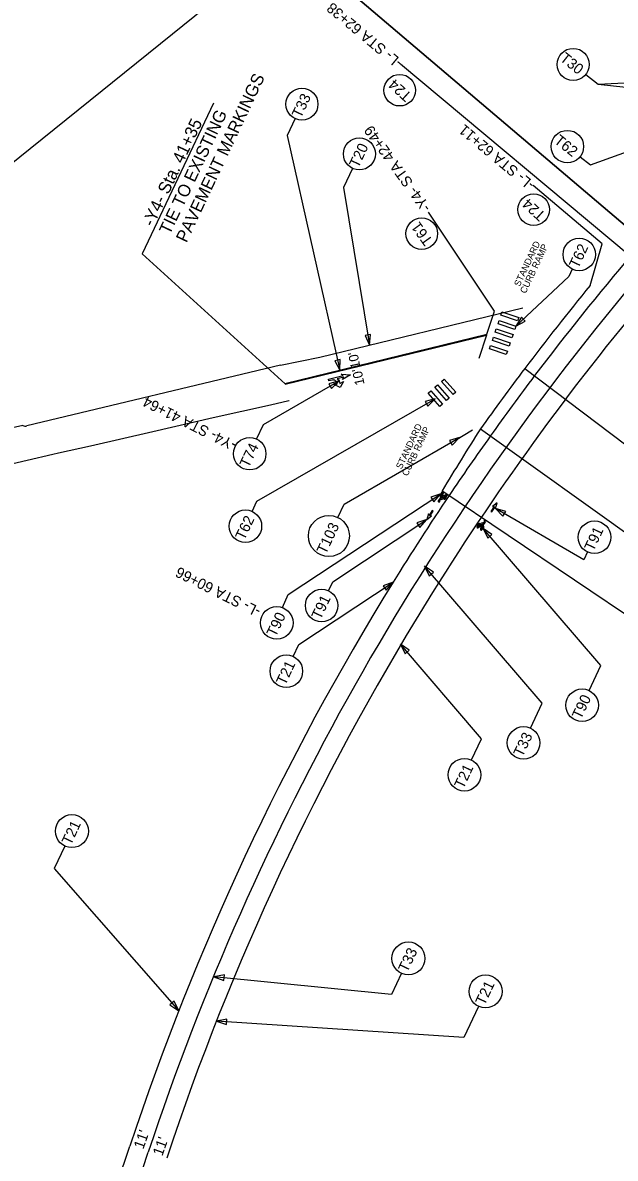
# Model space of a CAD drawing. Extents: x 553958 to 562499, y 493978 to 516388.
# Drawn here: x 557275 to 557610, y 506244 to 506887 of the extents above; entities that cross this region are included whole.
import ezdxf

# ---------------------------------------------------------------- set-up
doc = ezdxf.new("R2010")
doc.units = 0
for name, color, linetype in [('Prop Approach Slab', 7, 'Continuous'), ('Prop Conc 4in Sidewalk', 7, 'Continuous'), ('Prop Drainage Structure Gutter Shoulder Berm Label', 7, 'Continuous'), ('Prop EOT', 7, 'Continuous'), ('Prop Erosion Rip Rap Class II Label', 7, 'Continuous'), ('Prop Horizontal Alignment Tick Small', 7, 'Continuous'), ('Prop SS Fill Line', 7, 'Continuous'), ('Raster_Level_0', 7, 'Continuous'), ('Scratch_Level_0', 7, 'Continuous'), ('Scratch_Level_4', 7, 'Continuous'), ('Sheet North Arrow CELL', 7, 'Continuous'), ('Sheet Plan CELL', 7, 'Continuous'), ('Sheet Plot Border Inside CELL', 7, 'Continuous'), ('Sheet Plot Border Outside CELL', 7, 'Continuous')]:
    doc.layers.add(name, color=color, linetype=linetype)

msp = doc.modelspace()

# ---------------------------------------------------------------- linework, layer by layer
at = {"layer": 'Prop Approach Slab'}
for p, q in [((557618.37, 506754.68), (557488.54, 506863.27)), ((557602.58, 506761.69), (557563.47, 506794.66)), ((557541.75, 506723.58), (557504.29, 506779.54)), ((557595.82, 506738.04), (557602.58, 506761.69)), ((557537.19, 506709.89), (557541.75, 506723.58)), ((557558.78, 506691.06), (557680.67, 506599.06)), ((557533.69, 506656.92), (557657.57, 506568.52)), ((557511.85, 506622.13), (557636.11, 506538.44))]:
    msp.add_line(p, q, dxfattribs=at)
msp.add_lwpolyline([(557382.6, 506841.24), (557342.32, 506756.01), (557423.09, 506682.42)], dxfattribs=at)
at = {"layer": 'Prop Drainage Structure Gutter Shoulder Berm Label'}
msp.add_lwpolyline([(557447.66, 506685.08), (557456.08, 506687.13), (557454.86, 506687.94), (557460.17, 506687.61), (557455.6, 506684.87), (557456.32, 506686.16), (557452.65, 506685.27), (557453.12, 506684.91), (557453.4, 506684.61), (557453.66, 506684.22), (557453.83, 506683.88), (557454, 506683.44), (557454.17, 506682.63), (557456.2, 506683.81), (557454.36, 506680.45), (557450.33, 506682.21), (557452.64, 506682.26), (557452.47, 506682.89), (557452.36, 506683.26), (557452.18, 506683.61), (557451.93, 506683.89), (557451.66, 506684.18), (557451.24, 506684.42), (557450.76, 506684.57), (557450.27, 506684.61), (557449.74, 506684.57), (557447.9, 506684.11)], close=True, dxfattribs=at)
msp.add_lwpolyline([(557447.66, 506685.08), (557456.08, 506687.13), (557454.86, 506687.94), (557460.17, 506687.61), (557455.6, 506684.87), (557456.32, 506686.16), (557452.65, 506685.27), (557453.12, 506684.91), (557453.4, 506684.61), (557453.66, 506684.22), (557453.83, 506683.88), (557454, 506683.44), (557454.17, 506682.63), (557456.2, 506683.81), (557454.36, 506680.45), (557450.33, 506682.21), (557452.64, 506682.26), (557452.47, 506682.89), (557452.36, 506683.26), (557452.18, 506683.61), (557451.93, 506683.89), (557451.66, 506684.18), (557451.24, 506684.42), (557450.76, 506684.57), (557450.27, 506684.61), (557449.74, 506684.57), (557447.9, 506684.11)], close=True, dxfattribs=at)
at = {"layer": 'Prop EOT'}
for centre, start, end in [((558769.28, 505775.3), 139.54257, 142.88486), ((558763.69, 505779.29), 140.61603, 142.88486), ((558807.61, 505844.36), 147.46868, 149.02608), ((558769.28, 505775.3), 144.49155, 146.0414)]:
    msp.add_arc(centre, 1511, start, end, dxfattribs=at)
at = {"layer": 'Prop Erosion Rip Rap Class II Label'}
for points in [[(557425.46, 506933.59), (557889.73, 506539.36), (558124.72, 506519.69), (558557.87, 506177.2), (558959.56, 506684.21), (558454.57, 507154), (558185.43, 507366.81), (557535.46, 507286.55), (557335.3, 506986.11)], [(557510.24, 505740.54), (557854.59, 506431.05), (557889.73, 506539.36), (557425.46, 506933.59), (557046.6, 506628.46), (556899.98, 506318.25), (557006.57, 505850.3)]]:
    msp.add_lwpolyline(points, close=True, dxfattribs=at)
at = {"layer": 'Prop Horizontal Alignment Tick Small'}
for p, q in [((557510, 506616.36), (557509.87, 506616.44)), ((557510, 506616.36), (557509.87, 506616.44)), ((557510.4, 506616.73), (557511.23, 506618.18)), ((557510.72, 506616.63), (557510.4, 506616.73)), ((557512.01, 506616.99), (557510.72, 506616.63)), ((557511.39, 506617.84), (557510.85, 506616.89)), ((557510.85, 506616.89), (557512.18, 506617.24)), ((557511.23, 506618.18), (557512.91, 506619.46)), ((557511.26, 506620.24), (557511.47, 506620.11)), ((557511.26, 506620.24), (557511.47, 506620.11)), ((557512.39, 506617.65), (557511.39, 506617.84)), ((557513.06, 506619.27), (557511.47, 506618.06)), ((557511.47, 506618.06), (557512.24, 506617.92)), ((557512.18, 506617.24), (557512.01, 506616.99)), ((557512.15, 506619.66), (557512.35, 506619.53)), ((557512.15, 506619.66), (557512.35, 506619.53)), ((557512.24, 506617.92), (557512.47, 506618.53)), ((557512.7, 506618.44), (557512.39, 506617.65)), ((557512.47, 506618.53), (557512.7, 506618.44)), ((557512.91, 506619.46), (557513.08, 506619.29)), ((557513.31, 506618.9), (557513.51, 506618.77)), ((557513.31, 506618.9), (557513.51, 506618.77)), ((557514.2, 506618.32), (557514.4, 506618.19)), ((557514.2, 506618.32), (557514.4, 506618.19)), ((557510.81, 506615.82), (557510.69, 506615.91)), ((557510.81, 506615.82), (557510.69, 506615.91)), ((557535.67, 506603.92), (557534.34, 506603.57)), ((557534.34, 506603.57), (557534.51, 506603.83)), ((557534.51, 506603.83), (557535.81, 506604.18)), ((557535.13, 506602.98), (557535.67, 506603.92)), ((557536.12, 506604.09), (557535.29, 506602.64)), ((557535.71, 506604.99), (557535.84, 506604.91)), ((557535.71, 506604.99), (557535.84, 506604.91)), ((557535.81, 506604.18), (557536.12, 506604.09)), ((557536.52, 506604.46), (557536.65, 506604.37)), ((557536.52, 506604.46), (557536.65, 506604.37)), ((557532.33, 506602.49), (557532.12, 506602.63)), ((557532.33, 506602.49), (557532.12, 506602.63)), ((557533.21, 506601.91), (557533.01, 506602.05)), ((557533.21, 506601.91), (557533.01, 506602.05)), ((557533.61, 506601.35), (557533.44, 506601.53)), ((557533.46, 506601.54), (557535.05, 506602.75)), ((557535.29, 506602.64), (557533.61, 506601.35)), ((557533.83, 506602.37), (557534.13, 506603.16)), ((557534.05, 506602.29), (557533.83, 506602.37)), ((557534.28, 506602.89), (557534.05, 506602.29)), ((557534.13, 506603.16), (557535.13, 506602.98)), ((557534.37, 506601.15), (557534.17, 506601.29)), ((557534.37, 506601.15), (557534.17, 506601.29)), ((557535.05, 506602.75), (557534.28, 506602.89)), ((557535.26, 506600.57), (557535.05, 506600.71)), ((557535.26, 506600.57), (557535.05, 506600.71))]:
    msp.add_line(p, q, dxfattribs=at)
for points in [[(557506.06, 506607.79), (557505.14, 506607.63), (557507, 506610.47), (557506.47, 506610.82), (557504.61, 506607.98), (557504.38, 506608.89), (557503.44, 506605.63)], [(557506.06, 506607.79), (557505.14, 506607.63), (557507, 506610.47), (557506.47, 506610.82), (557504.61, 506607.98), (557504.38, 506608.89), (557503.44, 506605.63)], [(557540.54, 506612.98), (557541.46, 506613.13), (557539.58, 506610.3), (557540.11, 506609.95), (557541.99, 506612.78), (557542.22, 506611.86), (557543.17, 506615.12)], [(557540.54, 506612.98), (557541.46, 506613.13), (557539.58, 506610.3), (557540.11, 506609.95), (557541.99, 506612.78), (557542.22, 506611.86), (557543.17, 506615.12)]]:
    msp.add_lwpolyline(points, close=True, dxfattribs=at)
for centre, radius, start, end in [((557510.34, 506616.13), 0.563, 146.77541, 326.77541), ((557510.34, 506616.13), 0.563, 146.77541, 326.77541), ((557510.34, 506616.13), 0.41, 326.77541, 146.77541), ((557536.18, 506604.68), 0.563, 326.77541, 146.77541), ((557536.18, 506604.68), 0.563, 326.77541, 146.77541), ((557536.18, 506604.68), 0.41, 146.77541, 326.77541)]:
    msp.add_arc(centre, radius, start, end, dxfattribs=at)
for centre, major_axis, ratio, start_param, end_param in [((557511.81, 506619.88), (0.82, 1.25), 0.435841, 1.570796, 4.712389), ((557511.81, 506619.88), (0.69, 1.05), 0.325967, 1.570796, 4.712389), ((557511.81, 506619.88), (0.82, 1.25), 0.435841, 4.712389, 7.853982), ((557511.81, 506619.88), (0.69, 1.05), 0.325967, 4.712389, 7.853982), ((557513.85, 506618.54), (0.82, 1.25), 0.435841, 1.570796, 4.712389), ((557513.85, 506618.54), (0.69, 1.05), 0.325967, 1.570796, 4.712389), ((557513.85, 506618.54), (0.82, 1.25), 0.435841, 4.712389, 7.853982), ((557513.85, 506618.54), (0.69, 1.05), 0.325967, 4.712389, 7.853982), ((557532.67, 506602.27), (-0.82, -1.25), 0.435841, 1.570796, 4.712389), ((557532.67, 506602.27), (-0.69, -1.05), 0.325967, 1.570796, 4.712389), ((557532.67, 506602.27), (-0.82, -1.25), 0.435841, 4.712389, 7.853982), ((557532.67, 506602.27), (-0.69, -1.05), 0.325967, 4.712389, 7.853982), ((557534.71, 506600.93), (-0.82, -1.25), 0.435841, 4.712389, 7.853982), ((557534.71, 506600.93), (-0.69, -1.05), 0.325967, 4.712389, 7.853982), ((557534.71, 506600.93), (-0.82, -1.25), 0.435841, 1.570796, 4.712389), ((557534.71, 506600.93), (-0.69, -1.05), 0.325967, 1.570796, 4.712389)]:
    msp.add_ellipse(centre, major_axis=major_axis, ratio=ratio, start_param=start_param, end_param=end_param, dxfattribs=at)
at = {"layer": 'Prop SS Fill Line'}
for p, q in [((557442.74, 506697.49), (557557.73, 506725.42)), ((557420.51, 506693.08), (557442.74, 506697.49))]:
    msp.add_line(p, q, dxfattribs=at)
msp.add_arc((558769.28, 505775.3), 1511, 146.0414, 148.26076, dxfattribs=at)
at = {"layer": 'Raster_Level_0'}
msp.add_line((557333.73, 506211.9), (557345.67, 506247.87), dxfattribs=at)
msp.add_arc((558769.28, 505775.3), 1500, 139.54257, 161.63616, dxfattribs=at)
at = {"layer": 'Scratch_Level_0'}
msp.add_line((557274.6, 506658.9), (557246.99, 506652.72), dxfattribs=at)
for points in [[(557420.51, 506693.08), (557276.97, 506658.72)], [(557425.41, 506672.82), (557425.31, 506672.8), (557414.94, 506670.36), (557382.4, 506663.12), (557348.32, 506655.29), (557313.04, 506647.26), (557294.81, 506643.23), (557291.75, 506642.48), (557277.09, 506639.04), (557243.83, 506631.4), (557210.53, 506623.68)]]:
    msp.add_lwpolyline(points, dxfattribs=at)
msp.add_ellipse((557275.97, 506661.19), major_axis=(-0.49, -2.62), ratio=0.99957, start_param=5.926214, end_param=6.85226, dxfattribs=at)
at = {"layer": 'Scratch_Level_4'}
for points in [[(557545.9, 506723.15), (557555.37, 506719.93), (557554.73, 506718.04), (557545.26, 506721.26)], [(557542.7, 506713.55), (557552.17, 506710.34), (557551.52, 506708.44), (557542.06, 506711.66)], [(557544.31, 506718.29), (557553.78, 506715.07), (557553.13, 506713.18), (557543.67, 506716.39)], [(557541.09, 506708.82), (557550.56, 506705.6), (557549.92, 506703.71), (557540.45, 506706.92)], [(557539.48, 506704.08), (557548.95, 506700.87), (557548.31, 506698.97), (557538.84, 506702.19)], [(557514.5, 506673.05), (557507.85, 506680.52), (557509.34, 506681.85), (557515.99, 506674.38)], [(557518.23, 506676.37), (557511.58, 506683.84), (557513.08, 506685.17), (557519.73, 506677.7)], [(557510.71, 506669.6), (557504.06, 506677.07), (557505.56, 506678.4), (557512.2, 506670.93)]]:
    msp.add_lwpolyline(points, close=True, dxfattribs=at)
at = {"layer": 'Sheet North Arrow CELL'}
msp.add_line((557537.19, 506709.89), (557532.81, 506696.73), dxfattribs=at)
at = {"layer": 'Sheet Plan CELL'}
for points in [[(557593.34, 506857.45), (557600.29, 506851.96), (557666.76, 506855.36)], [(557593.34, 506857.45), (557600.29, 506851.96), (557682.25, 506843.15)], [(557428.81, 506832.44), (557424.29, 506822.89), (557454.13, 506690.22)], [(557590.14, 506810.92), (557596.04, 506806.25), (557658.21, 506828.7)], [(557461.3, 506804.28), (557456.15, 506793.39), (557470.95, 506704.34)], [(557585.71, 506747.29), (557583.74, 506743.12), (557553.78, 506715.07)], [(557407.04, 506651.21), (557410.94, 506659.47), (557453.75, 506684.05)], [(557404.47, 506610.26), (557407.21, 506616.07), (557508.13, 506674)], [(557452.92, 506606.88), (557456.53, 506614.44), (557521.93, 506651.99)], [(557421.74, 506555.84), (557424.94, 506563.27), (557511.26, 506620.24)], [(557594.31, 506587.34), (557592.15, 506582.81), (557542.22, 506611.86)], [(557447.75, 506565.36), (557450.16, 506570.47), (557503.44, 506605.63)], [(557595.2, 506508.99), (557601.86, 506523.08), (557535.26, 506600.57)], [(557562.06, 506487.68), (557568.72, 506501.76), (557502.12, 506579.25)], [(557427.77, 506528.22), (557430.97, 506535), (557484.25, 506570.17)], [(557528.59, 506469.68), (557534.36, 506481.68), (557488.43, 506535.12)], [(557298.46, 506421), (557292.49, 506408.36), (557362.94, 506327.85)], [(557488.93, 506349.03), (557483.28, 506337.08), (557382.83, 506347.13)], [(557532.61, 506330.35), (557524.31, 506312.8), (557384.25, 506321.93)]]:
    msp.add_lwpolyline(points, dxfattribs=at)
for points in [[(557556.95, 506720.16), (557553.78, 506715.07), (557559.07, 506717.9)], [(557468.47, 506709.8), (557470.95, 506704.34), (557471.54, 506710.31)], [(557451.34, 506695.53), (557454.13, 506690.22), (557454.37, 506696.21)], [(557449.49, 506679.81), (557453.75, 506684.05), (557447.95, 506682.51)], [(557503.88, 506669.77), (557508.13, 506674), (557502.33, 506672.47)], [(557517.68, 506647.76), (557521.93, 506651.99), (557516.13, 506650.45)], [(557507.28, 506615.75), (557511.26, 506620.24), (557505.57, 506618.34)], [(557548.01, 506610.29), (557542.22, 506611.86), (557546.44, 506607.61)], [(557499.46, 506601.14), (557503.44, 506605.63), (557497.75, 506603.74)], [(557540.21, 506597.19), (557535.26, 506600.57), (557537.86, 506595.17)], [(557507.08, 506575.87), (557502.12, 506579.25), (557504.72, 506573.85)], [(557480.27, 506565.68), (557484.25, 506570.17), (557478.56, 506568.27)], [(557493.39, 506531.73), (557488.43, 506535.12), (557491.03, 506529.71)], [(557388.75, 506348.1), (557382.83, 506347.13), (557388.44, 506345.01)], [(557357.95, 506331.19), (557362.94, 506327.85), (557360.29, 506333.24)], [(557390.14, 506323.1), (557384.25, 506321.93), (557389.93, 506320.01)]]:
    msp.add_lwpolyline(points, close=True, dxfattribs=at)
for centre, radius in [((557586.21, 506863.09), 9.09), ((557488.04, 506848.52), 8.94), ((557432.68, 506840.63), 9.06), ((557582.92, 506816.62), 9.19), ((557465.17, 506812.47), 9.06), ((557563.81, 506781), 8.94), ((557500.51, 506767.42), 8.94), ((557589.64, 506755.61), 9.19), ((557403.11, 506642.9), 9.19), ((557400.68, 506601.89), 9.19), ((557447.92, 506596.38), 11.62), ((557598.27, 506595.67), 9.22), ((557443.81, 506557.03), 9.22), ((557418.4, 506547.25), 9.22), ((557423.83, 506519.89), 9.22), ((557591.26, 506500.66), 9.22), ((557558.12, 506479.34), 9.22), ((557524.65, 506461.35), 9.22), ((557302.45, 506429.44), 9.34), ((557492.92, 506357.47), 9.34), ((557536.6, 506338.8), 9.34)]:
    msp.add_circle(centre, radius, dxfattribs=at)
at = {"layer": 'Sheet Plot Border Inside CELL'}
for p, q in [((557529.29, 506656.29), (557519.67, 506650.38)), ((557323.29, 506215.37), (557335.23, 506251.34))]:
    msp.add_line(p, q, dxfattribs=at)
for centre, radius, start, end in [((558771.28, 505774.06), 1491.35, 139.87766, 148.26076), ((558763.69, 505779.29), 1511, 142.88486, 144.49155), ((558769.28, 505775.3), 1511, 142.88486, 144.49155), ((558769.28, 505775.3), 1511, 148.26076, 161.63616), ((558769.28, 505775.3), 1489, 148.26076, 161.63616)]:
    msp.add_arc(centre, radius, start, end, dxfattribs=at)
at = {"layer": 'Sheet Plot Border Outside CELL'}
for p, q in [((557423.04, 506682.67), (557537.38, 506710.44)), ((557423.15, 506682.18), (557537.19, 506709.89))]:
    msp.add_line(p, q, dxfattribs=at)

# ---------------------------------------------------------------- texts
at = {"layer": 'Prop Approach Slab'}
for s, p in [('PAVEMENT MARKINGS', (557367.34, 506761.83)), ('TIE TO EXISTING', (557357.85, 506766.32)), ('-Y4- Sta. 41+35', (557348.35, 506770.81))]:
    msp.add_text(s, height=7, rotation=64.7021, dxfattribs=at).set_placement(p)
at = {"layer": 'Prop Conc 4in Sidewalk'}
for s, p in [('STANDARD ', (557555.89, 506737.13)), ('CURB RAMP', (557559.28, 506733.19)), ('STANDARD', (557489.04, 506633.85)), ('CURB RAMP', (557492.43, 506629.91))]:
    msp.add_text(s, height=3.75, rotation=64.7021, dxfattribs=at).set_placement(p)
at = {"layer": 'Prop EOT'}
for s, height, rotation, p in [("10'", 5.4, 101.81717, (557465.86, 506691.69)), ("10'", 5.4, 101.81717, (557468.15, 506682.21)), ("11'", 6, 70.37977, (557342.85, 506249.16)), ("11'", 6, 70.37977, (557353.6, 506245.26))]:
    msp.add_text(s, height=height, rotation=rotation, dxfattribs=at).set_placement(p)
at = {"layer": 'Sheet Plan CELL'}
for s, rotation, p in [('-L- STA 62+38', 140.15551, (557490.11, 506864.97)), ('T30', 321.66667, (557578.21, 506865.59)), ('T24', 137.58155, (557495.29, 506845.96)), ('T33', 64.7021, (557432.06, 506832.3)), ('-L- STA 62+11', 140.15551, (557564.91, 506796)), ('-Y4- STA 42+49', 125.7359, (557505.99, 506782.32)), ('T62', 321.66667, (557574.95, 506819.1)), ('T20', 64.7021, (557464.55, 506804.14)), ('T24', 137.58155, (557571.06, 506778.44)), ('T61', 125.7359, (557507.08, 506763.42)), ('T62', 64.7021, (557589.02, 506747.28)), ('-Y4- STA 41+64', 153.29519, (557396.22, 506649.66)), ('T74', 64.7021, (557402.49, 506634.57)), ('T62', 64.7021, (557400.06, 506593.56)), ('T103', 64.70206, (557446.15, 506585.61)), ('T91', 64.7021, (557597.63, 506587.31)), ('-L- STA 60+66', 153.29519, (557409.92, 506555.6)), ('T91', 64.7021, (557443.18, 506548.67)), ('T90', 64.7021, (557417.77, 506538.89)), ('T21', 64.7021, (557423.19, 506511.53)), ('T90', 64.7021, (557590.63, 506492.3)), ('T33', 64.7021, (557557.49, 506470.98)), ('T21', 64.7021, (557524.01, 506452.99)), ('T21', 64.69899, (557301.83, 506421.11)), ('T33', 64.69899, (557492.3, 506349.14)), ('T21', 64.69899, (557535.98, 506330.47))]:
    msp.add_text(s, height=6, rotation=rotation, dxfattribs=at).set_placement(p)

doc.saveas('drawing.dxf')
